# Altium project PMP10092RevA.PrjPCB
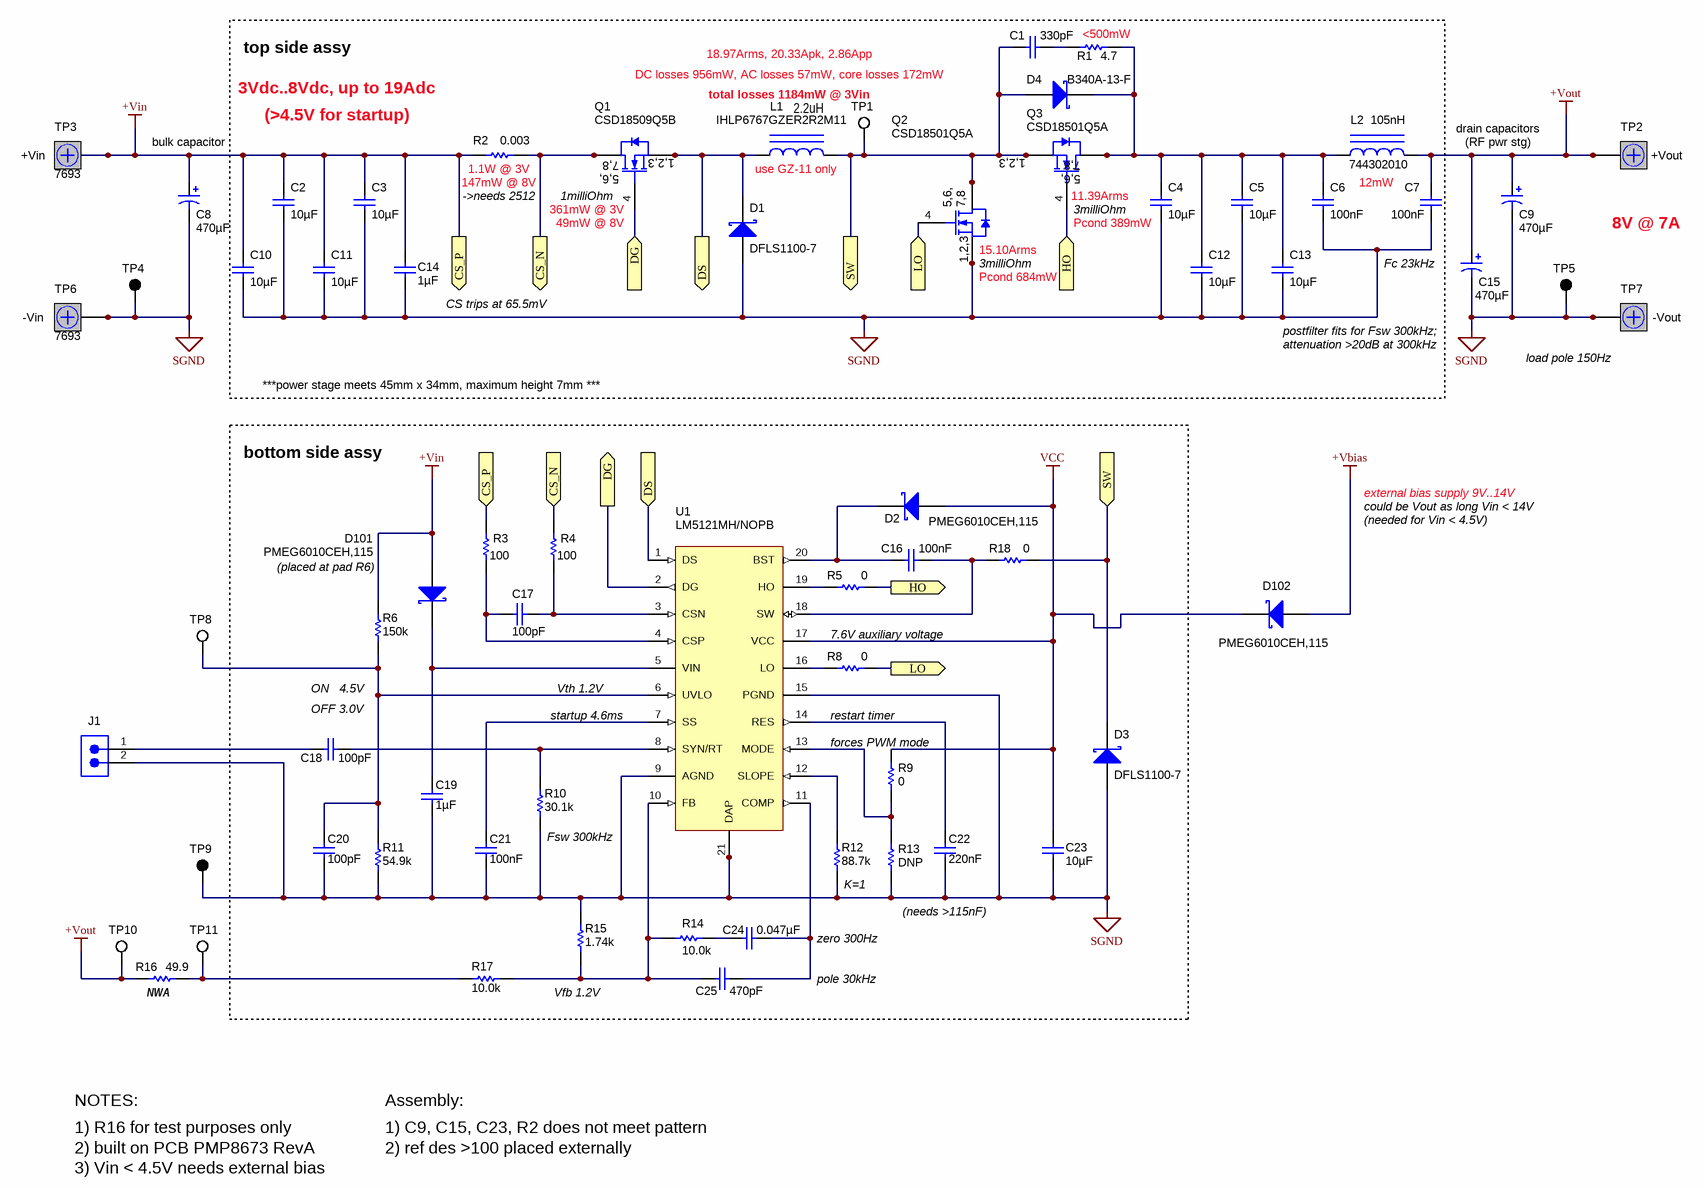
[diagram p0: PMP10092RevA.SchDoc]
CopyrightYear: 2014; PCB_Layout: B.Geck; PCB_Rev: A; PRJ_Engineer: B.Geck; PRJ_Number: PMP10092; PRJ_Title: Sync Boost w/ LM5121; SCH_Rev: A; TechSupport: http://www.ti.com/support
1 sheet, 66 parts. Net scope: flat (ports and power ports of the same name join across sheets).

## Sheet PMP10092RevA.SchDoc: 1 Ch Boost Converter
size 431 x 279 mm; Date: Not shown in title block; ApprovedBy: Not shown in title block; CheckedBy: Not shown in title block; Author: Not shown in title block; CompanyName: Not shown in title block; Organization: SVA PPD; Address1: Not shown in title block; Address2: Not shown in title block; Address3: Not shown in title block; Address4: Not shown in title block; DocumentNumber: 1; Revision: E1; SheetNumber: 1; SheetTotal: 1; PageSetup: Record=PageOptions¦CenterHorizontal=True¦CenterVertical=True¦PrintScale=0.77¦XCorrection=1.00¦YCorrection=1.00¦PrintKind=0¦BorderSize=5000000¦LeftOffset=0¦BottomOffset=0¦Orientation=2¦PaperLength=2794¦PaperWidth=2159¦Scale=100¦PaperSource=7¦PrintQuality=600¦MediaType=1¦DitherType=10¦PaperKind=A4¦PrintScaleMode=1

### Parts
C1  ValueDisplayed: 330pF  [0603]  (hidden comment: GRM188R72A331KA01D)
C2  ValueDisplayed: 10µF  [1210]  (hidden comment: GRM32ER71H106KA12L)
C3  ValueDisplayed: 10µF  [1210]  (hidden comment: GRM32ER71H106KA12L)
C4  ValueDisplayed: 10µF  [1210]  (hidden comment: GRM32ER71H106KA12L)
C5  ValueDisplayed: 10µF  [1210]  (hidden comment: GRM32ER71H106KA12L)
C6  ValueDisplayed: 100nF  [0805_HV]  (hidden comment: C2012X7R2A104K)
C7  ValueDisplayed: 100nF  [0805_HV]  (hidden comment: C2012X7R2A104K)
C8  ValueDisplayed: 470µF  [SM_RADIAL_J16]  (hidden comment: EEV-FK1J471M)
C9  ValueDisplayed: 470µF  [SM_RADIAL_J16]  (hidden comment: EEV-FK1J471M)
C10  ValueDisplayed: 10µF  [1210]  (hidden comment: GRM32ER71H106KA12L)
C11  ValueDisplayed: 10µF  [1210]  (hidden comment: GRM32ER71H106KA12L)
C12  ValueDisplayed: 10µF  [1210]  (hidden comment: GRM32ER71H106KA12L)
C13  ValueDisplayed: 10µF  [1210]  (hidden comment: GRM32ER71H106KA12L)
C14  ValueDisplayed: 1µF  [0805_HV]  (hidden comment: GRM21BR71H105KA12L)
C15  ValueDisplayed: 470µF  [SM_RADIAL_J16]  (hidden comment: EEV-FK1J471M)
C16  ValueDisplayed: 100nF  [0603]  (hidden comment: GRM188R71E104KA01D)
C17  ValueDisplayed: 100pF  [0603_HV]  (hidden comment: GRM1885C1H101JA01D)
C18  ValueDisplayed: 100pF  [0603_HV]  (hidden comment: GRM1885C1H101JA01D)
C19  ValueDisplayed: 1µF  [0805_HV]  (hidden comment: GRM21BR71H105KA12L)
C20  ValueDisplayed: 100pF  [0603_HV]  (hidden comment: GRM1885C1H101JA01D)
C21  ValueDisplayed: 100nF  [0603_HV]  (hidden comment: GRM188R71E104KA01D)
C22  ValueDisplayed: 220nF  [0603]  (hidden comment: GRM188R71E224KA88D)
C23  ValueDisplayed: 10µF  [0805_HV]  (hidden comment: GRM21BR61C106KE15L)
C24  ValueDisplayed: 0.047µF  [0603]  (hidden comment: GRM188R71H473KA61D)
C25  ValueDisplayed: 470pF  [0603]  (hidden comment: GRM188R71H471KA01D)
D1  DFLS1100-7  [powerDI123]
D2  PMEG6010CEH,115  [SOD-123F]
D3  DFLS1100-7  [powerDI123]
D4  B340A-13-F  [SMA]
D101  PMEG6010CEH,115  [SOD-123F]
D102  PMEG6010CEH,115  [SOD-123F]
J1  TSW-102-07-G-S  [TSW-102-07-G-S]  (value not drawn)
L1  IHLP6767GZER2R2M11  [IHLP-6767GZ-11]
L2  744302010  ValueDisplayed: 105nH  [IND_WE-HCM_7050]
Q1  CSD18509Q5B  [TRANS_NexFET_Q5B]
Q2  CSD18501Q5A  [TRANS_NexFET_Q5A]
Q3  CSD18501Q5A  [TRANS_NexFET_Q5A]
R1  value 4.7  [1206]  (hidden comment: CRCW12064R70JNEA)
R2  value 0.003  [2512M]  (hidden comment: 73M1R003F)
R3  value 100  [0603]  (hidden comment: CRCW0603100RFKEA)
R4  value 100  [0603]  (hidden comment: CRCW0603100RFKEA)
R5  value 0  [0603_HV]  (hidden comment: ERJ-3GEY0R00V)
R6  ValueDisplayed: 150k  [0603]  (hidden comment: CRCW0603150KFKEA)
R8  value 0  [0603_HV]  (hidden comment: ERJ-3GEY0R00V)
R9  value 0  [0603_HV]  (hidden comment: ERJ-3GEY0R00V)
R10  ValueDisplayed: 30.1k  [0603]  (hidden comment: CRCW060330K1FKEA)
R11  ValueDisplayed: 54.9k  [0603]  (hidden comment: CRCW060354K9FKEA)
R12  ValueDisplayed: 88.7k  [0603]  (hidden comment: CRCW060388K7FKEA)
R13  value DNP  [0603_HV]  (hidden comment: ERJ-3GEY0R00V)
R14  ValueDisplayed: 10.0k  [0603]  (hidden comment: CRCW060310K0FKEA)
R15  ValueDisplayed: 1.74k  [0603]  (hidden comment: CRCW06031K74FKEA)
R16  value 49.9  [0603]  (hidden comment: CRCW060349K9FKEA)
R17  ValueDisplayed: 10.0k  [0603]  (hidden comment: CRCW060310K0FKEA)
R18  value 0  [0603_HV]  (hidden comment: ERJ-3GEY0R00V)
TP1  5002  [Keystone5002]  (value not drawn)
TP2  7693  [7693]  (value not drawn)
TP3  7693  [7693]
TP4  5011  [Keystone5011]  (value not drawn)
TP5  5011  [Keystone5011]  (value not drawn)
TP6  7693  [7693]
TP7  7693  [7693]  (value not drawn)
TP8  5002  [Keystone5002]  (value not drawn)
TP9  5011  [Keystone5011]  (value not drawn)
TP10  5002  [Keystone5002]  (value not drawn)
TP11  5002  [Keystone5002]  (value not drawn)
U1  LM5121MH/NOPB  [PWP0020A_N]

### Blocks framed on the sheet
bottom side assy: C16-C25 D2 D3 D101 R3-R6 R8-R15 R17 R18 U1

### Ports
CS_N (in), CS_N (out), CS_P (in), CS_P (out), DG (in), DG (out), DS (in), DS (out), HO (in), HO (out), LO (in), LO (out), SW (in), SW (out)

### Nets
+Vbias: D102.2(A)
+Vin: C2.1 C3.1 C8.1(+) C10.1 C11.1 C14.1 D101.2(A) R2.1 R3.1 R6.2 TP3.1 TP3.2 TP3.3 TP3.4 ; port CS_P
+Vout: C7.1 C9.1(+) C15.1(+) L2.2 R16.1 TP2.1 TP2.2 TP2.3 TP2.4 TP10.1
SGND: C2.2 C3.2 C4.2 C5.2 C6.2 C7.2 C8.2(-) C9.2(-) C10.2 C11.2 C12.2 C13.2 C14.2 C15.2(-) C19.2 C20.2 C21.2 C22.2 C23.2 D1.2(A) D3.2(A) J1.2 Q2.1(S) Q2.2(S) Q2.3(S) R10.1 R11.1 R12.1 R13.1 R15.2 TP4.1 TP5.1 TP6.1 TP6.2 TP6.3 TP6.4 TP7.1 TP7.2 TP7.3 TP7.4 TP9.1 U1.9(AGND) U1.15(PGND) U1.21(DAP)
VCC: C23.1 D2.2(A) D102.1(K) R9.2 U1.17(VCC)
CS_N: Q1.5(D) Q1.6(D) Q1.7(D) Q1.8(D) R2.2 R4.1 ; port CS_N
DG: Q1.4(G) U1.2(DG) ; port DG
DS: D1.1(K) L1.1 Q1.1(S) Q1.2(S) Q1.3(S) U1.1(DS) ; port DS
HO: Q3.4(G) R5.1 ; port HO
LO: Q2.4(G) R8.2 ; port LO
SW: C1.2 D3.1(K) D4.2(A) L1.2 Q2.5(D) Q2.6(D) Q2.7(D) Q2.8(D) Q2.9(D) Q3.1(S) Q3.2(S) Q3.3(S) R18.1 TP1.1 ; port SW
NetC1_1: C1.1 R1.1
NetC4_1: C4.1 C5.1 C6.1 C12.1 C13.1 D4.1(K) L2.1 Q3.5(D) Q3.6(D) Q3.7(D) Q3.8(D) Q3.9(D) R1.2
NetC16_1: C16.1 R18.2 U1.18(SW)
NetC16_2: C16.2 D2.1(K) U1.20(BST)
NetC17_1: C17.1 R4.2 U1.3(CSN)
NetC17_2: C17.2 R3.2 U1.4(CSP)
NetC18_1: C18.1 R10.2 U1.8(SYN/RT)
NetC18_2: C18.2 J1.1
NetC19_1: C19.1 D101.1(K) U1.5(VIN)
NetC20_1: C20.1 R6.1 R11.2 TP8.1 U1.6(UVLO)
NetC21_1: C21.1 U1.7(SS)
NetC22_1: C22.1 U1.14(RES)
NetC24_1: C24.1 C25.1 U1.11(COMP)
NetC24_2: C24.2 R14.2
NetC25_2: C25.2 R14.1 R15.1 R17.2 U1.10(FB)
NetR5_2: R5.2 U1.19(HO)
NetR8_1: R8.1 U1.16(LO)
NetR9_1: R9.1 R13.2 U1.13(MODE)
NetR12_2: R12.2 U1.12(SLOPE)
NetR16_2: R16.2 R17.1 TP11.1

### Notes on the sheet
- top side assy
- 18.97Arms, 20.33Apk, 2.86App
- DC losses 956mW, AC losses 57mW, core losses 172mW
- (near R1) <500mW
- bulk capacitor
- 3Vdc..8Vdc, up to 19Adc
- (>4.5V for startup)
- (near TP1) total losses 1184mW @ 3Vin
- 2.2uH
- drain capacitors
- (RF pwr stg)
- (near TP3) +Vin
- (near R2) ->needs 2512
- (near R2) 1.1W @ 3V
- (near R2) 147mW @ 8V
- (near Q1) 1milliOhm
- (near Q1) 361mW @ 3V
- (near L1) use GZ-11 only
- 3milliOhm
- (near Q3) 11.39Arms
- (near L2) 12mW
- (near TP2) +Vout
- (near Q1) 49mW @ 8V
- (near Q2) 15.10Arms
- (near Q2) 3milliOhm
- (near Q2) Pcond 684mW
- Pcond 389mW
- Fc 23kHz
- 8V @ 7A
- (near TP6) -Vin
- (near C14) CS trips at 65.5mV
- postfilter fits for Fsw 300kHz;
- attenuation >20dB at 300kHz
- (near TP7) -Vout
- ***power stage meets 45mm x 34mm, maximum height 7mm ***
- (near TP7) load pole 150Hz
- external bias supply 9V..14V
- could be Vout as long Vin < 14V
- (needed for Vin < 4.5V)
- (placed at pad R6)
- ON   4.5V
- Vth 1.2V
- 7.6V auxiliary voltage
- (near C18) OFF 3.0V
- startup 4.6ms
- (near R9) forces PWM mode
- restart timer
- (near R10) Fsw 300kHz
- (near R12) K=1
- zero 300Hz
- (needs >115nF)
- (near R16) NWA
- Vfb 1.2V
- pole 30kHz
- 1) R16 for test purposes only
- NOTES:
- 2) built on PCB PMP8673 RevA
- Assembly:
- 1) C9, C15, C23, R2 does not meet pattern
- 2) ref des >100 placed externally
- 3) Vin < 4.5V needs external bias

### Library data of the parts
C1 = GRM188R72A331KA01D: CAP, CERM, 330pF, 100V, +/-10%, X7R, 0603; Manufacturer: MuRata; Polarized: N; CompType: Capacitor; U/M: EA; Cap_F: 0.00000000033; Tolerance_%: 10; Value1: Unknown; VDC_V: 100; TaMin_C: -55; TaMax_C: 125
C2-C5 C10-C13 = GRM32ER71H106KA12L: CAP, CERM, 10uF, 50V, +/-10%, X7R, 1210; Manufacturer: MuRata; Polarized: N; CompType: Capacitor; U/M: EA; Cap_F: 0.00001; Tolerance_%: 10; Value1: Unknown; VDC_V: 50; TaMin_C: -55; TaMax_C: 125
C6 C7 = C2012X7R2A104K: CAP, CERM, 0.1uF, 100V, +/-10%, X7R, 0805; Manufacturer: TDK; Polarized: N; CompType: Capacitor; U/M: EA; Cap_F: 0.0000001; Tolerance_%: 10; ESR_Ohm: 0.0158; Value1: 0.0158 ohm; VDC_V: 100; TaMin_C: -55; TaMax_C: 125; Cap_Case: 0805
C8 C9 C15 = EEV-FK1J471M: CAP, AL, 470uF, 63V, +/-20%, 0.082 ohm, SMD; Manufacturer: Panasonic; Polarized: Y; CompType: Capacitor; U/M: EA; Cap_F: 0.00047; Tolerance_%: 20; VDC_V: 63; ESR_Ohm: 0.082; IRMS_A: 1.41; TaMin_C: -55; TaMax_C: 105; Cap_Case: J16
C14 C19 = GRM21BR71H105KA12L: CAP, CERM, 1uF, 50V, +/-10%, X7R, 0805; Manufacturer: MuRata; Polarized: N; CompType: Capacitor; U/M: EA; Cap_F: 0.000001; Tolerance_%: 10; VDC_V: 50; TaMin_C: -55; TaMax_C: 125; Cap_Case: 0805
C16 = GRM188R71E104KA01D: CAP, CERM, 0.1uF, 25V, +/-10%, X7R, 0603; Manufacturer: MuRata; Polarized: N; CompType: Capacitor; U/M: EA; Cap_F: 0.0000001; Tolerance_%: 10; VDC_V: 25; TaMin_C: -55; TaMax_C: 125
C17 C18 C20 = GRM1885C1H101JA01D: CAP, CERM, 100pF, 50V, +/-5%, C0G/NP0, 0603; Manufacturer: MuRata; Polarized: N; CompType: Capacitor; U/M: EA; Cap_F: 0.0000000001; Tolerance_%: 5; VDC_V: 50; TaMin_C: -55; TaMax_C: 125; Cap_Case: 0603
C21 = GRM188R71E104KA01D: CAP, CERM, 0.1uF, 25V, +/-10%, X7R, 0603; Manufacturer: MuRata; Polarized: N; CompType: Capacitor; U/M: EA; Cap_F: 0.0000001; Tolerance_%: 10; VDC_V: 25; TaMin_C: -55; TaMax_C: 125; Cap_Case: 0603
C22 = GRM188R71E224KA88D: CAP, CERM, 0.22uF, 25V, +/-10%, X7R, 0603; Manufacturer: MuRata; Polarized: N; CompType: Capacitor; U/M: EA; Cap_F: 0.00000022; Tolerance_%: 10; Value1: Unknown; VDC_V: 25; TaMin_C: -55; TaMax_C: 125
C23 = GRM21BR61C106KE15L: CAP, CERM, 10 µF, 16 V, +/- 10%, X5R, 0805; Manufacturer: MuRata; Polarized: N; CompType: Capacitor; Value: 10uF; U/M: EA; Cap_F: 0.00001; Tolerance_%: 10; ESR_ohm: 0.008; Value1: 0.008 ohm; VDC_V: 16; Value2: 16V; TaMin_C: -55; TaMax_C: 85; Cap_Case: 0805
C24 = GRM188R71H473KA61D: CAP, CERM, 0.047 µF, 50 V, +/- 10%, X7R, 0603; Manufacturer: MuRata; Polarized: N; CompType: Capacitor; Value: 0.047uF; U/M: EA; Cap_F: 0.000000047; Tolerance_%: 10; Value1: Unknown; VDC_V: 50; Value2: 50V; TaMin_C: -55; TaMax_C: 125
C25 = GRM188R71H471KA01D: CAP, CERM, 470 pF, 50 V, +/- 10%, X7R, 0603; Manufacturer: MuRata; Polarized: N; CompType: Capacitor; Value: 470pF; U/M: EA; Cap_F: 0.00000000047; Tolerance_%: 10; Value1: Unknown; VDC_V: 50; Value2: 50V; TaMin_C: -55; TaMax_C: 125
D1 D3 = DFLS1100-7: Diode, Schottky, 100V, 1A, PowerDI123; Manufacturer: Diodes Inc.; Value: 0.77V; U/M: EA; Vf_V: 0.77; Io_A: 1; Vr_V: 100; TJmax_C: 175; RJC_CperW: 7
D2 D101 D102 = PMEG6010CEH,115: Diode, Schottky, 60V, 1A, SOD-123F; Manufacturer: NXP Semiconductor; U/M: EA; Vf_V: 0.57; Io_A: 1; Vr_V: 60; TJmax_C: 150; Value: 0.57V
D4 = B340A-13-F: Diode, Schottky, 40V, 3A, SMA; Manufacturer: Diodes Inc.; U/M: EA; Vf_V: 0.5; Value2: 0.5V; Io_A: 3; Vr_V: 40; TJmax_C: 125; RJC_CperW: 25
J1 = TSW-102-07-G-S: Header, TH, 100mil, 2x1, Gold plated, 230 mil above insulator; Manufacturer: Samtec, Inc.; U/M: EA
L1 = IHLP6767GZER2R2M11: Inductor, Shielded, Powdered Iron, 2.2uH, 28A, 0.00198 ohm, SMD; Manufacturer: Vishay-Dale; Ind_H: 2.2E-6; ValueDisplayed: 2.2µH; Imax_A: 28; Irms: 43.5A @ 40C rise; Isat: 28A @ 20% inductance drop
L2 = 744302010: Inductor, Shielded Drum Core, Ferrite, 105nH, 30A, 0.000235 ohm, SMD; Manufacturer: Wurth Elektronik eiSos; Ind_H: 105.0E-9; Imax_A: 30; Irms: 30A @ 50C rise; Isat: 45A @ 20% inductance drop; U/M: EA
Q1 = CSD18509Q5B: MOSFET, N-CH, 40V, 38A, SON 5x6mm; Manufacturer: Texas Instruments; Alternate Manufacturer: None; U/M: EA; ChType: N; VdsMax_V: 40; Value1: 0.0017 ohm; Rdson45_Ohm: 0.0017; Value2: 150 nC; QgTyp_nC: 150; Vgs_V: 20; IdsMax_A: 38
Q2 Q3 = CSD18501Q5A: MOSFET, N-CH, 40V, 22A, SON 5x6mm; Manufacturer: Texas Instruments; Alternate Manufacturer: None; U/M: EA; ChType: N; VdsMax_V: 40; Value1: 0.0043 ohm; Rdson45_Ohm: 0.0043; Value2: 20 nC; QgTyp_nC: 20; IdsMax_A: 22
R1 = CRCW12064R70JNEA: RES, 4.7 ohm, 5%, 0.25W, 1206; Manufacturer: Vishay-Dale; CompType: Resistor; Value_Code: 4R70; Tolerance_%: 5; Power_W: 0.25; VDC_V: 200; TempCo: 200 ppm/C; EIA_Code: E24; U/M: EA
R2 = 73M1R003F: RES, 0.003 ohm, 1%, 1W, 2512; Manufacturer: CTS Resistor; CompType: Resistor; Value_Code: R003; Tolerance_%: 1; TempCo: 300 ppm/C; EIA_Code: E96; U/M: EA
R3 R4 = CRCW0603100RFKEA: RES, 100 ohm, 1%, 0.1W, 0603; Manufacturer: Vishay-Dale; CompType: Resistor; Value_Code: 100R; Tolerance_%: 1; Power_W: 0.1; VDC_V: 75; TempCo: 100 ppm/C; EIA_Code: E96; U/M: EA
R5 R8 R9 R18 = ERJ-3GEY0R00V: RES, 0 ohm, 5%, 0.1W, 0603; Manufacturer: Panasonic; CompType: Resistor; Value_Code: 0000; Tolerance_%: 5; Power_W: 0.1; VDC_V: 50; TempCo: 600 ppm/C; EIA_Code: E24; U/M: EA
R6 = CRCW0603150KFKEA: RES, 150 k, 1%, 0.1 W, 0603; Manufacturer: Vishay-Dale; CompType: Resistor; Value: 150k; Res_ohm: 150000; Tolerance_%: 1; Power_W: 0.1; Value2: 0.1W; VDC_V: 75; TempCo: 100 ppm/C; EIA_Code: E96; U/M: EA
R10 = CRCW060330K1FKEA: RES, 30.1 k, 1%, 0.1 W, 0603; Manufacturer: Vishay-Dale; CompType: Resistor; Value: 30.1k; Res_ohm: 30100; Value_Code: 30k1; Tolerance_%: 1; Power_W: 0.1; Value2: 0.1W; VDC_V: 75; TempCo: 100 ppm/C; EIA_Code: E96; U/M: EA
R11 = CRCW060354K9FKEA: RES, 54.9 k, 1%, 0.1 W, 0603; Manufacturer: Vishay-Dale; CompType: Resistor; Value: 54.9k; Res_ohm: 54900; Value_Code: 54k9; Tolerance_%: 1; Power_W: 0.1; Value2: 0.1W; VDC_V: 75; TempCo: 100 ppm/C; EIA_Code: E96; U/M: EA
R12 = CRCW060388K7FKEA: RES, 88.7 k, 1%, 0.1 W, 0603; Manufacturer: Vishay-Dale; CompType: Resistor; Value: 88.7k; Res_ohm: 88700; Value_Code: 88k7; Tolerance_%: 1; Power_W: 0.1; Value2: 0.1W; VDC_V: 75; TempCo: 100 ppm/C; EIA_Code: E96; U/M: EA
R13 = ERJ-3GEY0R00V: RES, 0 ohm, 5%, 0.1W, 0603; Manufacturer: Panasonic; CompType: Resistor; Res_ohm: 0; Value_Code: 0000; Tolerance_%: 5; Power_W: 0.1; VDC_V: 50; TempCo: 600 ppm/C; EIA_Code: E24; U/M: EA
R14 R17 = CRCW060310K0FKEA: RES, 10.0 k, 1%, 0.1 W, 0603; Manufacturer: Vishay-Dale; CompType: Resistor; Value: 10.0k; Res_ohm: 10000; Value_Code: 10k0; Tolerance_%: 1; Power_W: 0.1; Value2: 0.1W; VDC_V: 75; TempCo: 100 ppm/C; EIA_Code: E96; U/M: EA
R15 = CRCW06031K74FKEA: RES, 1.74 k, 1%, 0.1 W, 0603; Manufacturer: Vishay-Dale; CompType: Resistor; Value: 1.74k; Res_ohm: 1740; Value_Code: 1k74; Tolerance_%: 1; Power_W: 0.1; Value2: 0.1W; VDC_V: 75; TempCo: 100 ppm/C; EIA_Code: E96; U/M: EA
R16 = CRCW060349K9FKEA: RES, 49.9k ohm, 1%, 0.1W, 0603; Manufacturer: Vishay-Dale; CompType: Resistor; Res_ohm: 49900; Value_Code: 49k9; Tolerance_%: 1; Power_W: 0.1; VDC_V: 75; TempCo: 100 ppm/C; EIA_Code: E96; U/M: EA
TP1 TP8 TP10 TP11 = 5002: Test Point, TH, Miniature, White; Manufacturer: Keystone; CompType: Test Point Loop; U/M: EA
TP2 TP3 TP6 TP7 = 7693: Terminal screw, vertical, snap-in; Manufacturer: Keystone; CompType: Screw Terminal; U/M: EA; Value: 15A; SymbolCreator: codlsc
TP4 TP5 TP9 = 5011: Test Point, TH, Multipurpose, Black; Manufacturer: Keystone; CompType: Test Point Loop; U/M: EA
U1 = LM5121MH/NOPB: Wide Input Synchronous Boost Controller with Disconnection Switch Control, PWP0020A; Alternate Manufacturer: None; Manufacturer: Texas Instruments; SymbolCreator: a0411947; CompType: IC; U/M: EA

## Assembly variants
001: all parts fitted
